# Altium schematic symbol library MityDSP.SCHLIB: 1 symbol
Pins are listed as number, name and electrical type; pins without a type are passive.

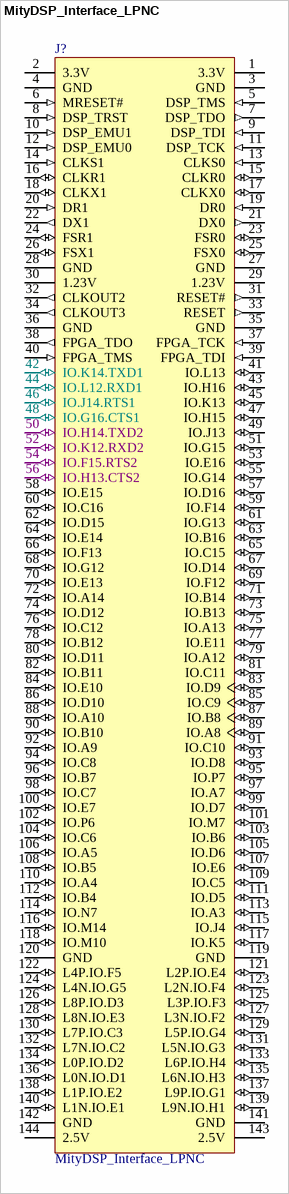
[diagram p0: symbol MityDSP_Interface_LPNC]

## MityDSP_Interface_LPNC
designator J?
CONN MEMORY SOCKET 144POS DIMM; Mfg: Tyco Electronics; Mfg_PN: 390111-1; User: MikeP; Dist1: Digi-Key; Dist1_PN: A99608-ND; $/10: 5.960000; $/100: 3.842500; $/500: 3.524500; $/1000: 3.445000; dist_PID: 4997; dist_pref: 100; ID: 4330; Mfg_PID: 4980; PbFree_Status: Lead free; QtyAvail: 591
footprint 390111-1_LPNC (MityDSP Socket No Clip)
pins: 0, 1 3.3V (power), 2 3.3V (power), 3 GND (power), 4 GND (power), 5 DSP_TMS (in), 6 MRESET# (in), 7 DSP_TDO (out), 8 DSP_TRST (in), 9 DSP_TDI (in), 10 DSP_EMU1 (in), 11 DSP_TCK (in), 12 DSP_EMU0 (in), 13 CLKS0 (in), 14 CLKS1 (in), 15 CLKR0 (io), 16 CLKR1 (io), 17 CLKX0 (io), 18 CLKX1 (io), 19 DR0 (in), 20 DR1 (in), 21 DX0 (out), 22 DX1 (out), 23 FSR0 (io), 24 FSR1 (io), 25 FSX0 (io), 26 FSX1 (io), 27 GND (power), 28 GND (power), 29 1.23V (power), 30 1.23V (power), 31 RESET# (out), 32 CLKOUT2 (out), 33 RESET (out), 34 CLKOUT3 (out), 35 GND (power), 36 GND (power), 37 FPGA_TCK (in), 38 FPGA_TDO (out), 39 FPGA_TDI (in), 40 FPGA_TMS (in), 41 IO.L13 (io) "FPGA_IO", 42 IO.K14.TXD1 (io) "FPGA_IO", 43 IO.H16 (io) "FPGA_IO", 44 IO.L12.RXD1 (io) "FPGA_IO", 45 IO.K13 (io) "FPGA_IO", 46 IO.J14.RTS1 (io) "FPGA_IO", 47 IO.H15 (io) "FPGA_IO", 48 IO.G16.CTS1 (io) "FPGA_IO", 49 IO.J13 (io) "FPGA_IO", 50 IO.H14.TXD2 (io) "FPGA_IO", 51 IO.G15 (io) "FPGA_IO", 52 IO.K12.RXD2 (io) "FPGA_IO", 53 IO.E16 (io) "FPGA_IO", 54 IO.F15.RTS2 (io) "FPGA_IO", 55 IO.G14 (io) "FPGA_IO", 56 IO.H13.CTS2 (io) "FPGA_IO", 57 IO.D16 (io) "FPGA_IO", 58 IO.E15 (io) "FPGA_IO", 59 IO.F14 (io) "FPGA_IO", 60 IO.C16 (io) "FPGA_IO", 61 IO.G13 (io) "FPGA_IO", 62 IO.D15 (io) "FPGA_IO", 63 IO.B16 (io) "FPGA_IO", 64 IO.E14 (io) "FPGA_IO", 65 IO.C15 (io) "FPGA_IO", 66 IO.F13 (io) "FPGA_IO", 67 IO.D14 (io) "FPGA_IO", 68 IO.G12 (io) "FPGA_IO", 69 IO.F12 (io) "FPGA_IO", 70 IO.E13 (io) "FPGA_IO", 71 IO.B14 (io) "FPGA_IO", 72 IO.A14 (io) "FPGA_IO", 73 IO.B13 (io) "FPGA_IO", 74 IO.D12 (io) "FPGA_IO", 75 IO.A13 (io) "FPGA_IO", 76 IO.C12 (io) "FPGA_IO", 77 IO.E11 (io) "FPGA_IO", 78 IO.B12 (io) "FPGA_IO", 79 IO.A12 (io) "FPGA_IO", 80 IO.D11 (io) "FPGA_IO", 81 IO.C11 (io) "FPGA_IO", 82 IO.B11 (io) "FPGA_IO", 83 IO.D9 (io) "FPGA_IO", 84 IO.E10 (io) "FPGA_IO", 85 IO.C9 (io) "FPGA_IO", 86 IO.D10 (io) "FPGA_IO", 87 IO.B8 (io) "FPGA_IO", 88 IO.A10 (io) "FPGA_IO", 89 IO.A8 (io) "FPGA_IO", 90 IO.B10 (io) "FPGA_IO", 91 IO.C10 (io) "FPGA_IO", 92 IO.A9 (io) "FPGA_IO", 93 IO.D8 (io) "FPGA_IO", 94 IO.C8 (io) "FPGA_IO", 95 IO.P7 (io) "FPGA_IO", 96 IO.B7 (io) "FPGA_IO", 97 IO.A7 (io) "FPGA_IO", 98 IO.C7 (io) "FPGA_IO", 99 IO.D7 (io) "FPGA_IO", 100 IO.E7 (io) "FPGA_IO", 101 IO.M7 (io) "FPGA_IO", 102 IO.P6 (io) "FPGA_IO", 103 IO.B6 (io) "FPGA_IO", 104 IO.C6 (io) "FPGA_IO", 105 IO.D6 (io) "FPGA_IO", 106 IO.A5 (io) "FPGA_IO", 107 IO.E6 (io) "FPGA_IO", 108 IO.B5 (io) "FPGA_IO", 109 IO.C5 (io) "FPGA_IO", 110 IO.A4 (io) "FPGA_IO", 111 IO.D5 (io) "FPGA_IO", 112 IO.B4 (io) "FPGA_IO", 113 IO.A3 (io) "FPGA_IO", 114 IO.N7 (io) "FPGA_IO", 115 IO.J4 (io) "FPGA_IO", 116 IO.M14 (io) "FPGA_IO", 117 IO.K5 (io) "FPGA_IO", 118 IO.M10 (io) "FPGA_IO", 119 GND (power), 120 GND (power), 121 L2P.IO.E4 (io) "LVDS/FPGA_IO", 122 L4P.IO.F5 (io) "LVDS/FPGA_IO", 123 L2N.IO.F4 (io) "LVDS/FPGA_IO", 124 L4N.IO.G5 (io) "LVDS/FPGA_IO", 125 L3P.IO.F3 (io) "LVDS/FPGA_IO", 126 L8P.IO.D3 (io) "LVDS/FPGA_IO", 127 L3N.IO.F2 (io) "LVDS/FPGA_IO", 128 L8N.IO.E3 (io) "LVDS/FPGA_IO", 129 L5P.IO.G4 (io) "LVDS/FPGA_IO", 130 L7P.IO.C3 (io) "LVDS/FPGA_IO", 131 L5N.IO.G3 (io) "LVDS/FPGA_IO", 132 L7N.IO.C2 (io) "LVDS/FPGA_IO", 133 L6P.IO.H4 (io) "LVDS/FPGA_IO", 134 L0P.IO.D2 (io) "LVDS/FPGA_IO", 135 L6N.IO.H3 (io) "LVDS/FPGA_IO", 136 L0N.IO.D1 (io) "LVDS/FPGA_IO", 137 L9P.IO.G1 (io) "LVDS/FPGA_IO", 138 L1P.IO.E2 (io) "LVDS/FPGA_IO", 139 L9N.IO.H1 (io) "LVDS/FPGA_IO", 140 L1N.IO.E1 (io) "LVDS/FPGA_IO", 141 GND (power), 142 GND (power), 143 2.5V (power), 144 2.5V (power)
